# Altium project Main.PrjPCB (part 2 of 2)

## Sheet Main-6.SchDoc: #
size A3; ApprovedBy: #; DrawnBy: #; DocumentNumber: 6; Revision: #; SheetNumber: 6; DocumentRevision: #; Reviewed: #; QA: #; CM: #; ECR: #; PageSetup: Record=PageOptions¦CenterHorizontal=True¦CenterVertical=True¦PrintScale=0.97¦XCorrection=1.00¦YCorrection=1.00¦PrintKind=1¦BorderSize=5000000¦LeftOffset=0¦BottomOffset=0¦Orientation=2¦PaperLength=1000¦PaperWidth=1000¦Scale=100¦PaperSource=7¦PrintQuality=-4¦MediaType=1¦DitherType=10¦PaperKind=A3¦PrintScaleMode=1
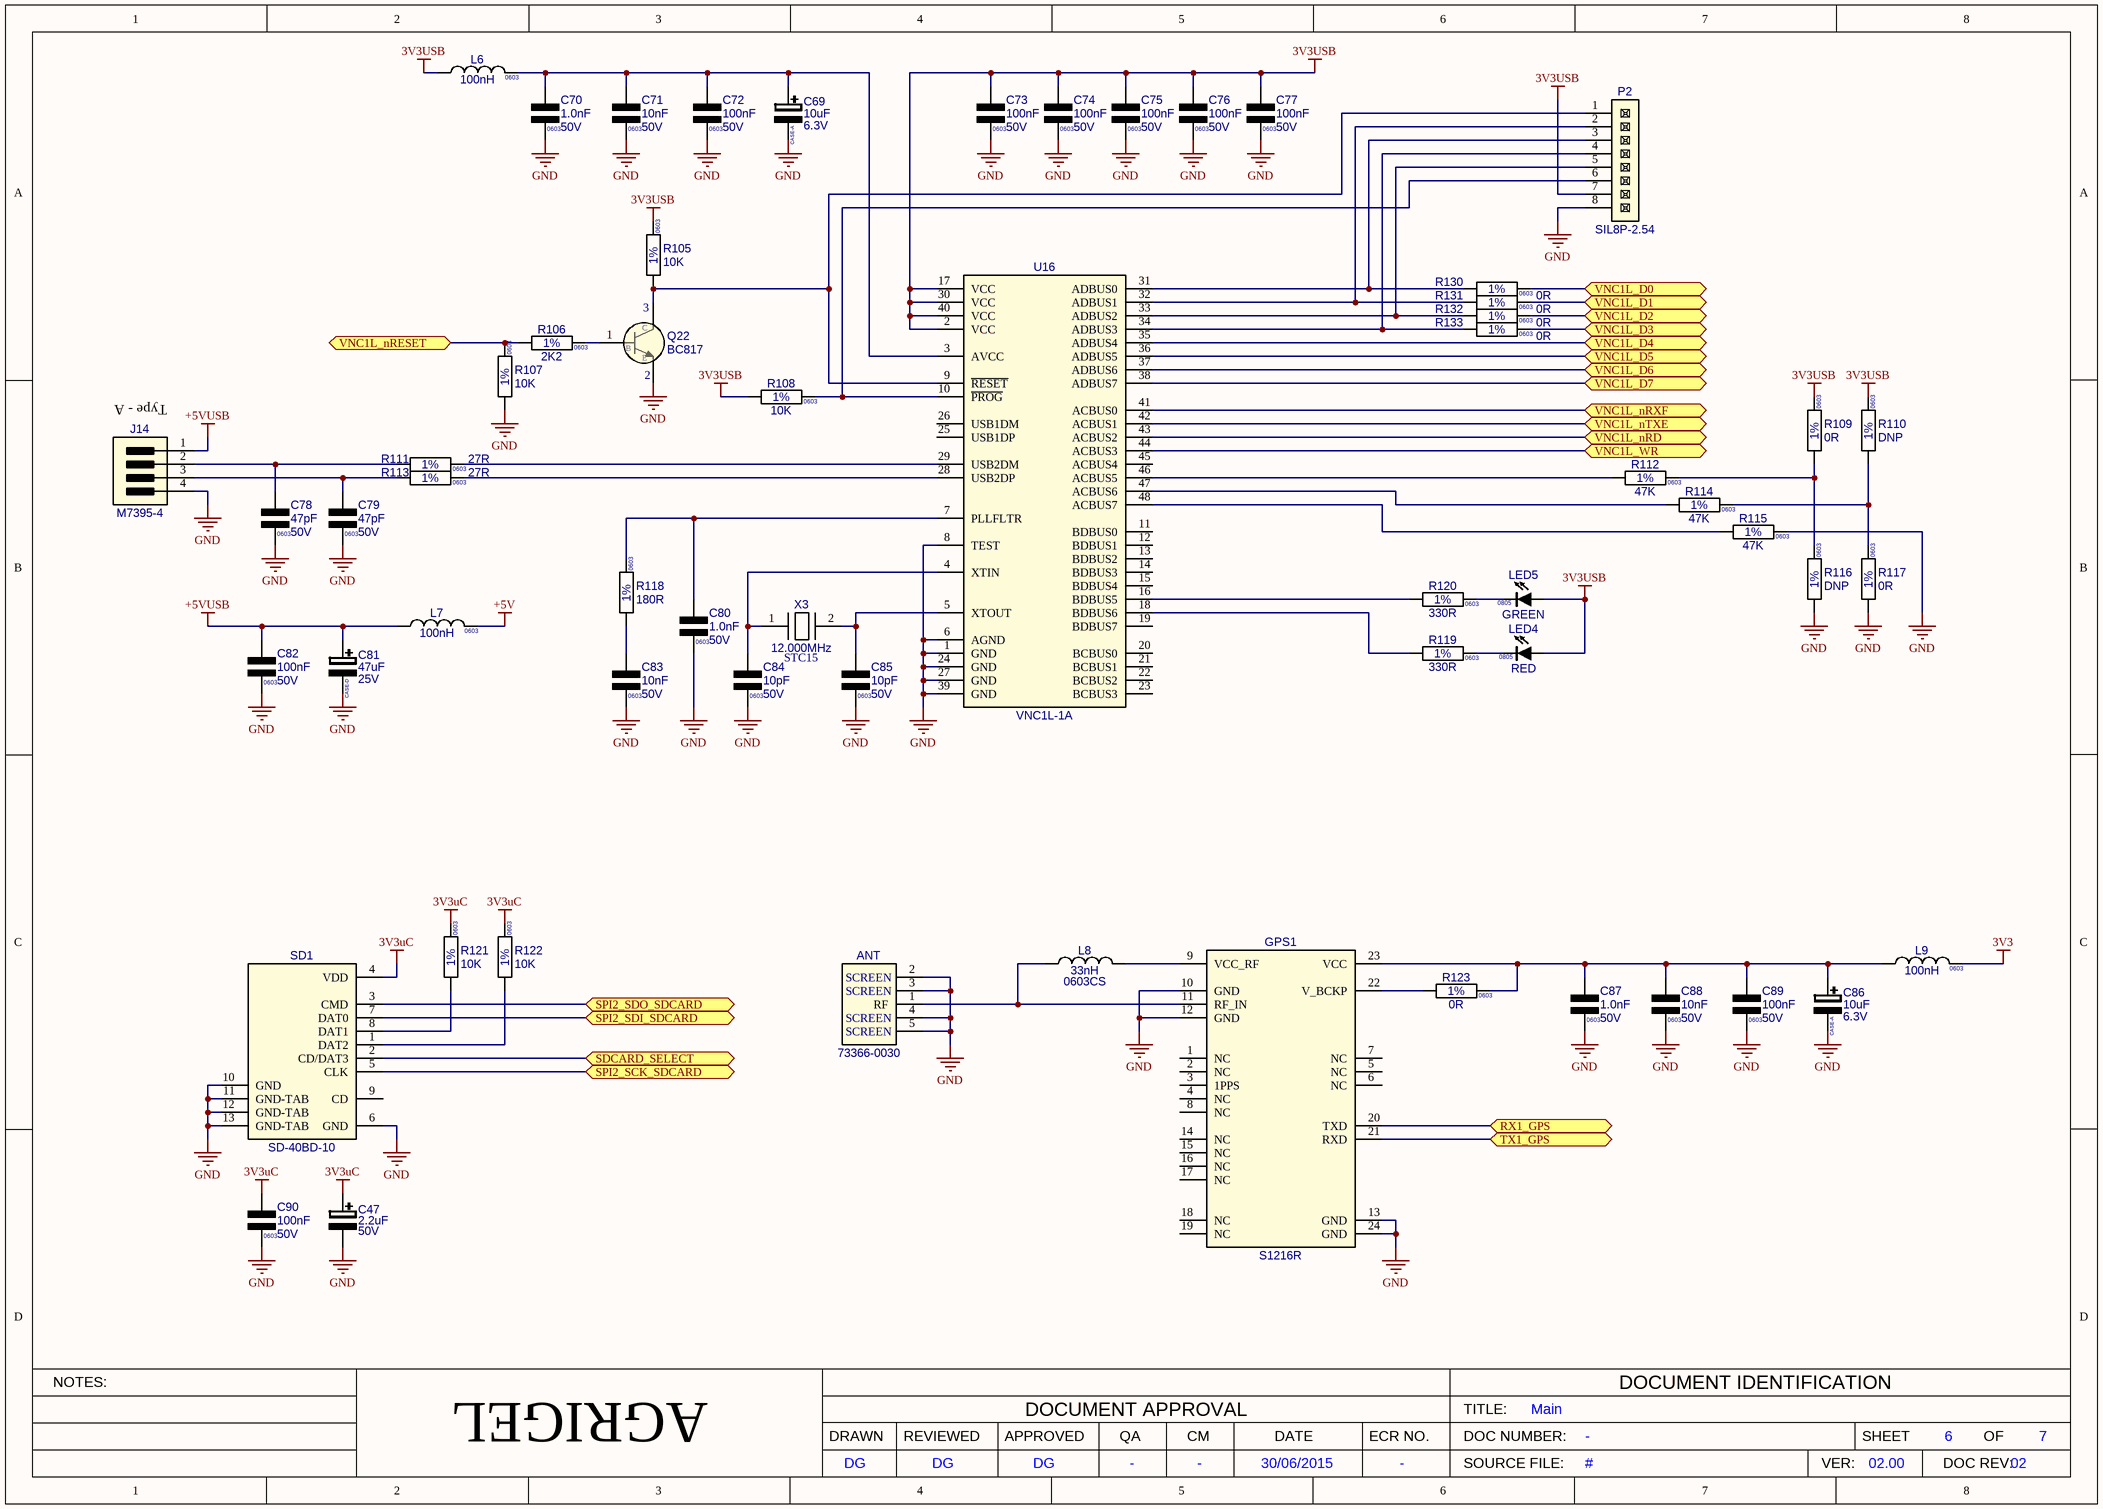
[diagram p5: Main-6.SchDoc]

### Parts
ANT  Part Number: 73366-0030  [MCX-RT-733660030]  (hidden comment: Coax-MCX-RT)
C47  value 2.2uF  Voltage: 50V  [CAP-EL-SMD-4X5.4]  (hidden comment: 2.2uF-50V-20%_4x5.4)
C69  value 10uF  Voltage: 6.3V  Text1: CASE-A  [T491-A]  (hidden comment: 10uF_6.3V_T491A_20%)
C70  value 1.0nF  Voltage: 50V  Text1: 0603  [CAPC0603X85N]  (hidden comment: 1.0nF_C0603_50V_10%_X7R)
C71  value 10nF  Voltage: 50V  Text1: 0603  [CAPC0603X85N]  (hidden comment: 10nF_C0603_50V_10%_X7R)
C72  value 100nF  Voltage: 50V  Text1: 0603  [CAPC0603X85N]  (hidden comment: 100nF_C0603_50V_5%_X7R)
C73  value 100nF  Voltage: 50V  Text1: 0603  [CAPC0603X85N]  (hidden comment: 100nF_C0603_50V_5%_X7R)
C74  value 100nF  Voltage: 50V  Text1: 0603  [CAPC0603X85N]  (hidden comment: 100nF_C0603_50V_5%_X7R)
C75  value 100nF  Voltage: 50V  Text1: 0603  [CAPC0603X85N]  (hidden comment: 100nF_C0603_50V_5%_X7R)
C76  value 100nF  Voltage: 50V  Text1: 0603  [CAPC0603X85N]  (hidden comment: 100nF_C0603_50V_5%_X7R)
C77  value 100nF  Voltage: 50V  Text1: 0603  [CAPC0603X85N]  (hidden comment: 100nF_C0603_50V_5%_X7R)
C78  value 47pF  Voltage: 50V  Text1: 0603  [CAPC0603X85N]  (hidden comment: 47pF_C0603_50V_10%_NP0)
C79  value 47pF  Voltage: 50V  Text1: 0603  [CAPC0603X85N]  (hidden comment: 47pF_C0603_50V_10%_NP0)
C80  value 1.0nF  Voltage: 50V  Text1: 0603  [CAPC0603X85N]  (hidden comment: 1.0nF_C0603_50V_10%_X7R)
C81  value 47uF  Voltage: 25V  Text1: CASE-D  [T491-D]  (hidden comment: 47uF_25V_T491D_20%)
C82  value 100nF  Voltage: 50V  Text1: 0603  [CAPC0603X85N]  (hidden comment: 100nF_C0603_50V_5%_X7R)
C83  value 10nF  Voltage: 50V  Text1: 0603  [CAPC0603X85N]  (hidden comment: 10nF_C0603_50V_10%_X7R)
C84  value 10pF  Voltage: 50V  Text1: 0603  [CAPC0603X85N]  (hidden comment: 10pF_C0603_50V_5%_NP0)
C85  value 10pF  Voltage: 50V  Text1: 0603  [CAPC0603X85N]  (hidden comment: 10pF_C0603_50V_5%_NP0)
C86  value 10uF  Voltage: 6.3V  Text1: CASE-A  [T491-A]  (hidden comment: 10uF_6.3V_T491A_20%)
C87  value 1.0nF  Voltage: 50V  Text1: 0603  [CAPC0603X85N]  (hidden comment: 1.0nF_C0603_50V_10%_X7R)
C88  value 10nF  Voltage: 50V  Text1: 0603  [CAPC0603X85N]  (hidden comment: 10nF_C0603_50V_10%_X7R)
C89  value 100nF  Voltage: 50V  Text1: 0603  [CAPC0603X85N]  (hidden comment: 100nF_C0603_50V_5%_X7R)
C90  value 100nF  Voltage: 50V  Text1: 0603  [CAPC0603X85N]  (hidden comment: 100nF_C0603_50V_5%_X7R)
GPS1  S1216R  [S1216R]
J14  M7395-4  [M7395-4]
L6  value 100nH  Text1: 0603  [L0603]  (hidden comment: 100nH-CI160808)
L7  value 100nH  Text1: 0603  [L0603]  (hidden comment: 100nH-CI160808)
L8  value 33nH  Text2: 0603CS  [L0603CS]  (hidden comment: 33nH-0603CS)
L9  value 100nH  Text1: 0603  [L0603]  (hidden comment: 100nH-CI160808)
LED4  value RED  Text2: 0805  [LED0805-Red]  (hidden comment: RED_0805_SMD)
LED5  value GREEN  Text2: 0805  [LED0805-Green]  (hidden comment: GREEN_0805_SMD)
P2  SIL8P-2.54  [SIL8P-2.54]
Q22  BC817  [SOT23]
R105  value 10K  Tol: 1%  Text1: 0603  [RESC0603X60N]  (hidden comment: 10K_R0603_1%)
R106  value 2K2  Tol: 1%  Text1: 0603  [RESC0603X60N]  (hidden comment: 2K2_R0603_1%)
R107  value 10K  Tol: 1%  Text1: 0603  [RESC0603X60N]  (hidden comment: 10K_R0603_1%)
R108  value 10K  Tol: 1%  Text1: 0603  [RESC0603X60N]  (hidden comment: 10K_R0603_1%)
R109  value 0R  Tol: 1%  Text1: 0603  [RESC0603X60N]  (hidden comment: 0R_R0603_1%)
R110  value DNP  Tol: 1%  Text1: 0603  [RESC0603X60N]  (hidden comment: DNP_R0603_1%)
R111  value 27R  Tol: 1%  Text1: 0603  [RESC0603X60N]  (hidden comment: 27R_R0603_1%)
R112  value 47K  Tol: 1%  Text1: 0603  [RESC0603X60N]  (hidden comment: 47K_R0603_1%)
R113  value 27R  Tol: 1%  Text1: 0603  [RESC0603X60N]  (hidden comment: 27R_R0603_1%)
R114  value 47K  Tol: 1%  Text1: 0603  [RESC0603X60N]  (hidden comment: 47K_R0603_1%)
R115  value 47K  Tol: 1%  Text1: 0603  [RESC0603X60N]  (hidden comment: 47K_R0603_1%)
R116  value DNP  Tol: 1%  Text1: 0603  [RESC0603X60N]  (hidden comment: DNP_R0603_1%)
R117  value 0R  Tol: 1%  Text1: 0603  [RESC0603X60N]  (hidden comment: 0R_R0603_1%)
R118  value 180R  Tol: 1%  Text1: 0603  [RESC0603X60N]  (hidden comment: 180R_R0603_1%)
R119  value 330R  Tol: 1%  Text1: 0603  [RESC0603X60N]  (hidden comment: 330R_R0603_1%)
R120  value 330R  Tol: 1%  Text1: 0603  [RESC0603X60N]  (hidden comment: 330R_R0603_1%)
R121  value 10K  Tol: 1%  Text1: 0603  [RESC0603X60N]  (hidden comment: 10K_R0603_1%)
R122  value 10K  Tol: 1%  Text1: 0603  [RESC0603X60N]  (hidden comment: 10K_R0603_1%)
R123  value 0R  Tol: 1%  Text1: 0603  [RESC0603X60N]  (hidden comment: 0R_R0603_1%)
R130  value 0R  Tol: 1%  Text1: 0603  [RESC0603X60N]  (hidden comment: 0R_R0603_1%)
R131  value 0R  Tol: 1%  Text1: 0603  [RESC0603X60N]  (hidden comment: 0R_R0603_1%)
R132  value 0R  Tol: 1%  Text1: 0603  [RESC0603X60N]  (hidden comment: 0R_R0603_1%)
R133  value 0R  Tol: 1%  Text1: 0603  [RESC0603X60N]  (hidden comment: 0R_R0603_1%)
SD1  SD-40BD-10  [SD-40BD-10]
U16  VNC1L-1A  [LQFP48-7x7]
X3  Text2: STC15  Text1: 12.000MHz  [XT-HEX15]  (hidden comment: XTAL_12.000MHz_STCX15)

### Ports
RX1_GPS, SDCARD_SELECT, SPI2_SCK_SDCARD, SPI2_SDI_SDCARD, SPI2_SDO_SDCARD, TX1_GPS, VNC1L_D0, VNC1L_D1, VNC1L_D2, VNC1L_D3, VNC1L_D4, VNC1L_D5, VNC1L_D6, VNC1L_D7, VNC1L_nRD, VNC1L_nRESET, VNC1L_nRXF, VNC1L_nTXE, VNC1L_WR

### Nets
3V3: L9.2
3V3uC: C47.1 C90.1 R121.1 R122.1 SD1.4(VDD)
3V3USB: C73.1 C74.1 C75.1 C76.1 C77.1 L6.1 LED4.2(A) LED5.2(A) P2.7 R105.1 R108.1 R109.1 R110.1 U16.2(VCC) U16.17(VCC) U16.30(VCC) U16.40(VCC)
+5V: L7.2
+5VUSB: C81.1 C82.1 J14.1 L7.1
GND: ANT.2(SCREEN) ANT.3(SCREEN) ANT.4(SCREEN) ANT.5(SCREEN) C47.2 C69.2 C70.2 C71.2 C72.2 C73.2 C74.2 C75.2 C76.2 C77.2 C78.2 C79.2 C80.2 C81.2 C82.2 C83.2 C84.2 C85.2 C86.2 C87.2 C88.2 C89.2 C90.2 GPS1.10(GND) GPS1.12(GND) GPS1.13(GND) GPS1.24(GND) J14.4 P2.8 Q22.2(E) R107.2 R115.2 R116.2 R117.2 SD1.6(GND) SD1.10(GND) SD1.11(GND-TAB) SD1.12(GND-TAB) SD1.13(GND-TAB) U16.1(GND) U16.6(AGND) U16.8(TEST) U16.24(GND) U16.27(GND) U16.39(GND)
NetANT_1: ANT.1(RF) GPS1.11(RF_IN) L8.1
NetC69_1: C69.1 C70.1 C71.1 C72.1 L6.2 U16.3(AVCC)
NetC78_1: C78.1 J14.2 R111.1
NetC79_1: C79.1 J14.3 R113.1
NetC80_1: C80.1 R118.1 U16.7(PLLFLTR)
NetC83_1: C83.1 R118.2
NetC84_1: C84.1 U16.4(XTIN) X3.1
NetC85_1: C85.1 U16.5(XTOUT) X3.2
NetC86_1: C86.1 C87.1 C88.1 C89.1 GPS1.23(VCC) L9.1 R123.2
NetGPS1_9: GPS1.9(VCC_RF) L8.2
NetGPS1_20: GPS1.20(TXD) ; port RX1_GPS
NetGPS1_21: GPS1.21(RXD) ; port TX1_GPS
NetGPS1_22: GPS1.22(V_BCKP) R123.1
NetLED4_1: LED4.1(K) R119.2
NetLED5_1: LED5.1(K) R120.2
NetP2_1: P2.1 Q22.3(C) R105.2 U16.9(~{RESET})
NetP2_2: P2.2 R131.1 U16.32(ADBUS1)
NetP2_3: P2.3 R130.1 U16.31(ADBUS0)
NetP2_4: P2.4 R133.1 U16.34(ADBUS3)
NetP2_5: P2.5 R132.1 U16.33(ADBUS2)
NetP2_6: P2.6 R108.2 U16.10(~{PROG})
NetQ22_1: Q22.1(B) R106.2
NetR106_1: R106.1 R107.1 ; port VNC1L_nRESET
NetR109_2: R109.2 R112.2 R116.1
NetR110_2: R110.2 R114.2 R117.1
NetR111_2: R111.2 U16.29(USB2DM)
NetR112_1: R112.1 U16.46(ACBUS5)
NetR113_2: R113.2 U16.28(USB2DP)
NetR114_1: R114.1 U16.47(ACBUS6)
NetR115_1: R115.1 U16.48(ACBUS7)
NetR119_1: R119.1 U16.18(BDBUS6)
NetR120_1: R120.1 U16.16(BDBUS5)
NetR121_2: R121.2 SD1.8(DAT1)
NetR122_2: R122.2 SD1.1(DAT2)
NetR130_2: R130.2 ; port VNC1L_D0
NetR131_2: R131.2 ; port VNC1L_D1
NetR132_2: R132.2 ; port VNC1L_D2
NetR133_2: R133.2 ; port VNC1L_D3
NetSD1_2: SD1.2(CD/DAT3) ; port SDCARD_SELECT
NetSD1_3: SD1.3(CMD) ; port SPI2_SDO_SDCARD
NetSD1_5: SD1.5(CLK) ; port SPI2_SCK_SDCARD
NetSD1_7: SD1.7(DAT0) ; port SPI2_SDI_SDCARD
NetU3_53: U16.43(ACBUS2) ; port VNC1L_nRD
NetU3_54: U16.44(ACBUS3) ; port VNC1L_WR
NetU3_55: U16.42(ACBUS1) ; port VNC1L_nTXE
NetU3_65: U16.35(ADBUS4) ; port VNC1L_D4
NetU3_66: U16.36(ADBUS5) ; port VNC1L_D5
NetU3_67: U16.37(ADBUS6) ; port VNC1L_D6
NetU3_68: U16.38(ADBUS7) ; port VNC1L_D7
NetU3_72: U16.41(ACBUS0) ; port VNC1L_nRXF

Not connected (* = marked no-connect by the designer): GPS1 1(NC) 2(NC) 3(1PPS) 4(NC) 5(NC) 6(NC) 7(NC) 8(NC) 14(NC) 15(NC) 16(NC) 17(NC) 18(NC) 19(NC); SD1 9(CD); U16 11(BDBUS0) 12(BDBUS1) 13(BDBUS2) 14(BDBUS3) 15(BDBUS4) 19(BDBUS7) 20(BCBUS0) 21(BCBUS1) 22(BCBUS2) 23(BCBUS3) 25(USB1DP) 26(USB1DM) 45(ACBUS4)

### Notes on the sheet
- (near J14) Type - A

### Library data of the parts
ANT = Coax-MCX-73366-0030: Connector Coax MCX Rt Angle 50Ohm; Manufacturer: Molex; Board Tech: THP
C47 = 2.2uF-50V-20%_4x5.4_V: Cap Electrolytic SMD (4x5.4); Manufacturer: Various; Part Number: Cap El SMD 2.2uF-50V-20%_4x5.4; Tol: 20%
C69 C86 = 10uF_6.3V_CASE-A_20%_V: Cap Tantalum Case-A; Manufacturer: Various; Board Tech: SMD; Tol: 20%
C70 C80 C87 = 1nF_0603N_50V_10%_X7R_V: Cap Ceramic X7R; Manufacturer: Various; Part Number: 1.0nF 0603 50V 10% X7R; Board Tech: SMD; Tol: 10%; Reutech PN: 5910-CA-0401
C71 C83 C88 = 10nF_0603N_50V_10%_X7R_V: Cap Ceramic X7R; Manufacturer: Various; Part Number: 10nF 0603 50V 10% X7R; Board Tech: SMD; Tol: 10%; Reutech PN: 5910-CA-0402
C72-C77 C82 C89 C90 = 100nF_0603N_50V_5%_X7R_V: Cap Ceramic X7R; Manufacturer: Various; Part Number: 100nF 0603 50V 5% X7R; Board Tech: SMD; Tol: 5%; Reutech PN: 5910-CA-0433
C78 C79 = 47pF_0603N_50V_10%_NP0_V: Cap Ceramic NP0; Manufacturer: Various; Part Number: 47pF 0603 50V 10% NP0; Board Tech: SMD; Tol: 10%
C81 = 47uF_25V_CASE-D_20%_V: Cap Tantalum Case-D; Manufacturer: Various; Board Tech: SMD; Tol: 20%
C84 C85 = 10pF_0603N_50V_5%_NP0_V: Cap Ceramic NP0; Manufacturer: Various; Part Number: 10pF 0603 50V 5% NP0; Board Tech: SMD; Tol: 5%
GPS1 = S1216R GPS Receiver: Module GPS Receiver; Manufacturer: SkyTraq; Board Tech: SMD
J14 = M7395-4: Header Pluggable 2.54mm Rt Angle Friction Lock; Manufacturer: Molex; Board Tech: THP
L6 L7 L9 = 100nH_CI160808_H: Inductor Chip SMD; Manufacturer: Bourns; Part Number: CI160808-R10J; Tol: 5%
L8 = 33nH_0603CS_5%_H: Inductor Chip SMD; Manufacturer: COILCRAFT; Part Number: 0603CS-33NXJL; Tol: 5%
LED4 = RED_0805_SMD_H: LED SMD 0805 Red; Manufacturer: Various; EDM-PN: LED7
LED5 = GREEN_0805_SMD_H: LED SMD 0805 Green; Manufacturer: Various; EDM-PN: LED17
P2 = SIL8P-2.54: Header SIL Male THP, 2.54mm Pitch; Manufacturer: Various
Q22 = BC817_SOT23: Transistor NPN General Purpose; Manufacturer: Various; Board Tech: SMD; EDM-PN: TRN12
R105 R107 R121 R122 = 10K_0603_V: Resistor Chip SMD; Manufacturer: Various; Part Number: 10K 0603 1%; Watt: 100mW; EDM-PN: RES120
R106 = 2K2_0603_H: Resistor Chip SMD; Manufacturer: Various; Part Number: 2K2 0603 1%; Watt: 100mW; EDM-PN: RES232
R108 = 10K_0603_H: Resistor Chip SMD; Manufacturer: Various; Part Number: 10K 0603 1%; Watt: 100mW; EDM-PN: RES120
R109 R117 = 0R_0603_V: Resistor Chip SMD; Manufacturer: Various; Part Number: 0R 0603 1%; Watt: 100mW; EDM-PN: RES117
R110 R116 = DNP_0603_V: Resistor Chip SMD; Manufacturer: Various; Watt: 100mW
R111 R113 = 27R_0603_H: Resistor Chip SMD; Manufacturer: Various; Part Number: 27R 0603 1%; Watt: 100mW; EDM-PN: RES619
R112 R114 R115 = 47K_0603_H: Resistor Chip SMD; Manufacturer: Various; Part Number: 47K 0603 1%; Watt: 100mW; EDM-PN: RES128
R118 = 180R_0603_V: Resistor Chip SMD; Manufacturer: Various; Part Number: 180R 0603 1%; Watt: 100mW
R119 R120 = 330R_0603_H: Resistor Chip SMD; Manufacturer: Various; Part Number: 330R 0603 1%; Watt: 100mW
R123 = 0R_0603_H: Resistor Chip SMD; Manufacturer: Various; Part Number: 0R 0603 1%; Watt: 100mW; EDM-PN: RES117
R130-R133 = 0r_0603_H: Resistor Chip SMD; Manufacturer: Various; Part Number: 0R 0603 1%; Watt: 100mW; EDM-PN: RES117
SD1 = SD-40BD-10: SD Micro Push-Push; Manufacturer: Speccon; Board Tech: SMD
U16 = VNC1L-1A-LQFP48: IC Dual USB Host Controller; Manufacturer: FTDI; Board Tech: SMT
X3 = XTAL_12.000MHz_STCX15: Crystal - HEX15; Manufacturer: STC; Part Number: STCX15-12.000MHz; Board Tech: SMD; Value: XTAL_STCX15-12.000MHz

## Sheet Main-7.SchDoc: #
size A3; ApprovedBy: #; DrawnBy: #; DocumentNumber: 7; Revision: #; SheetNumber: 7; DocumentRevision: #; Reviewed: #; QA: #; CM: #; ECR: #; PageSetup: Record=PageOptions|CenterHorizontal=True|CenterVertical=True|PrintScale=0.97|XCorrection=1.00|YCorrection=1.00|PrintKind=1|BorderSize=5000000|LeftOffset=0|BottomOffset=0|Orientation=2|PaperLength=1000|PaperWidth=1000|Scale=100|PaperSource=7|PrintQuality=-4|MediaType=1|DitherType=10|PaperKind=A3|PrintScaleMode=1
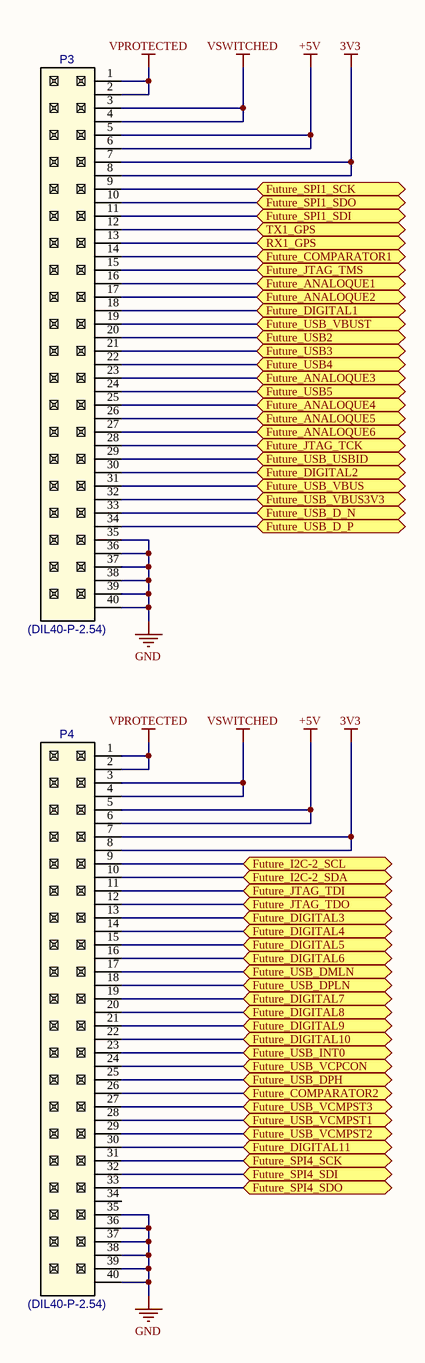
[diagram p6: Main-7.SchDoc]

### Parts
P3  value (DIL40-P-2.54)  [DIL40-P-2.54]  (hidden comment: DIL40P-2.54-DNF)
P4  value (DIL40-P-2.54)  [DIL40-P-2.54]  (hidden comment: DIL40P-2.54-DNF)

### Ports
Future_ANALOQUE1, Future_ANALOQUE2, Future_ANALOQUE3, Future_ANALOQUE4, Future_ANALOQUE5, Future_ANALOQUE6, Future_COMPARATOR1, Future_COMPARATOR2, Future_DIGITAL1, Future_DIGITAL2, Future_DIGITAL3, Future_DIGITAL4, Future_DIGITAL5, Future_DIGITAL6, Future_DIGITAL7, Future_DIGITAL8, Future_DIGITAL9, Future_DIGITAL10, Future_DIGITAL11, Future_I2C-2_SCL, Future_I2C-2_SDA, Future_JTAG_TCK, Future_JTAG_TDI, Future_JTAG_TDO, Future_JTAG_TMS, Future_SPI1_SCK, Future_SPI1_SDI, Future_SPI1_SDO, Future_SPI4_SCK, Future_SPI4_SDI, Future_SPI4_SDO, Future_USB2, Future_USB3, Future_USB4, Future_USB5, Future_USB_D_N, Future_USB_D_P, Future_USB_DMLN, Future_USB_DPH, Future_USB_DPLN, Future_USB_INT0, Future_USB_USBID, Future_USB_VBUS, Future_USB_VBUS3V3, Future_USB_VBUST, Future_USB_VCMPST1, Future_USB_VCMPST2, Future_USB_VCMPST3, Future_USB_VCPCON, RX1_GPS, TX1_GPS

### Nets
3V3: P3.7 P3.8 P4.7 P4.8
+5V: P3.5 P3.6 P4.5 P4.6
GND: P3.35 P3.36 P3.37 P3.38 P3.39 P3.40 P4.35 P4.36 P4.37 P4.38 P4.39 P4.40
VPROTECTED: P3.1 P3.2 P4.1 P4.2
VSWITCHED: P3.3 P3.4 P4.3 P4.4
NetGPS1_20: P3.13 ; port RX1_GPS
NetGPS1_21: P3.12 ; port TX1_GPS
NetP3_9: P3.9 ; port Future_SPI1_SCK
NetP3_10: P3.10 ; port Future_SPI1_SDO
NetP3_11: P3.11 ; port Future_SPI1_SDI
NetP3_14: P3.14 ; port Future_COMPARATOR1
NetP3_15: P3.15 ; port Future_JTAG_TMS
NetP3_16: P3.16 ; port Future_ANALOQUE1
NetP3_17: P3.17 ; port Future_ANALOQUE2
NetP3_18: P3.18 ; port Future_DIGITAL1
NetP3_19: P3.19 ; port Future_USB_VBUST
NetP3_20: P3.20 ; port Future_USB2
NetP3_21: P3.21 ; port Future_USB3
NetP3_22: P3.22 ; port Future_USB4
NetP3_23: P3.23 ; port Future_ANALOQUE3
NetP3_24: P3.24 ; port Future_USB5
NetP3_25: P3.25 ; port Future_ANALOQUE4
NetP3_26: P3.26 ; port Future_ANALOQUE5
NetP3_27: P3.27 ; port Future_ANALOQUE6
NetP3_28: P3.28 ; port Future_JTAG_TCK
NetP3_29: P3.29 ; port Future_USB_USBID
NetP3_30: P3.30 ; port Future_DIGITAL2
NetP3_31: P3.31 ; port Future_USB_VBUS
NetP3_32: P3.32 ; port Future_USB_VBUS3V3
NetP3_33: P3.33 ; port Future_USB_D_N
NetP3_34: P3.34 ; port Future_USB_D_P
NetP4_9: P4.9 ; port Future_I2C-2_SCL
NetP4_10: P4.10 ; port Future_I2C-2_SDA
NetP4_11: P4.11 ; port Future_JTAG_TDI
NetP4_12: P4.12 ; port Future_JTAG_TDO
NetP4_13: P4.13 ; port Future_DIGITAL3
NetP4_14: P4.14 ; port Future_DIGITAL4
NetP4_15: P4.15 ; port Future_DIGITAL5
NetP4_16: P4.16 ; port Future_DIGITAL6
NetP4_17: P4.17 ; port Future_USB_DMLN
NetP4_18: P4.18 ; port Future_USB_DPLN
NetP4_19: P4.19 ; port Future_DIGITAL7
NetP4_20: P4.20 ; port Future_DIGITAL8
NetP4_21: P4.21 ; port Future_DIGITAL9
NetP4_22: P4.22 ; port Future_DIGITAL10
NetP4_23: P4.23 ; port Future_USB_INT0
NetP4_24: P4.24 ; port Future_USB_VCPCON
NetP4_25: P4.25 ; port Future_USB_DPH
NetP4_26: P4.26 ; port Future_COMPARATOR2
NetP4_27: P4.27 ; port Future_USB_VCMPST3
NetP4_28: P4.28 ; port Future_USB_VCMPST1
NetP4_29: P4.29 ; port Future_USB_VCMPST2
NetP4_30: P4.30 ; port Future_DIGITAL11
NetP4_31: P4.31 ; port Future_SPI4_SCK
NetP4_32: P4.32 ; port Future_SPI4_SDI
NetP4_33: P4.33 ; port Future_SPI4_SDO

Not connected (* = marked no-connect by the designer): P4 34

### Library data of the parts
P3 P4 = DIL40P-2.54-DNF: Header Male Straight, 2.54mm Pitch - Do not Fit; Manufacturer: Various; Part Number: DNF - DIL40-P-2.54; Board Tech: THP

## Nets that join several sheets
3V3: Main-1 (7 pins), Main-6 (L9.2), Main-7 (P3.7 P3.8 P4.7 P4.8)
3V3uC: Main-1 (5 pins), Main-2 (21 pins), Main-4 (20 pins), Main-6 (5 pins)
3V3USB: Main-1 (5 pins), Main-6 (17 pins)
+5V: Main-1 (C4.1 L1.2 R2.1 R3.1), Main-2 (R15.1), Main-3 (12 pins), Main-5 (19 pins), Main-6 (L7.2), Main-7 (P3.5 P3.6 P4.5 P4.6)
GND: Main-1 (37 pins), Main-2 (30 pins), Main-3 (47 pins), Main-4 (28 pins), Main-5 (32 pins), Main-6 (49 pins), Main-7 (12 pins)
VPROTECTED: Main-1 (8 pins), Main-5 (K2.4 K2.13 Q19.2 R96.1), Main-7 (P3.1 P3.2 P4.1 P4.2)
VSLAVES: Main-1 (K1.8 K1.9), Main-3 (J5.1 J7.1)
VSWITCHED: Main-1 (D5.2 D8.2), Main-2 (R16.1), Main-3 (5 pins), Main-5 (6 pins), Main-7 (P3.3 P3.4 P4.3 P4.4)
NetD16_2: Main-2 (U3.6), Main-5 (D16.2)
NetD18_2: Main-2 (U3.7), Main-5 (D18.2)
NetD21_2: Main-2 (U3.8), Main-5 (D21.2)
NetD23_2: Main-2 (U3.9), Main-5 (D23.2)
NetGPS1_20: Main-2 (U3.10), Main-6 (GPS1.20), Main-7 (P3.13)
NetGPS1_21: Main-2 (U3.5), Main-6 (GPS1.21), Main-7 (P3.12)
NetLCD1_4: Main-2 (U3.119), Main-5 (LCD1.4 R75.2)
NetLCD1_5: Main-2 (U3.114), Main-5 (LCD1.5 R76.2)
NetLCD1_6: Main-2 (U3.113), Main-5 (LCD1.6 R77.2)
NetLCD1_7: Main-2 (U3.115), Main-5 (LCD1.7 R78.2)
NetLCD1_8: Main-2 (U3.116), Main-5 (LCD1.8 R79.2)
NetLCD1_9: Main-2 (U3.117), Main-5 (LCD1.9 R80.2)
NetLCD1_10: Main-2 (U3.118), Main-5 (LCD1.10 R81.2)
NetLCD1_11: Main-2 (U3.132), Main-5 (LCD1.11 R82.2)
NetLCD1_12: Main-2 (U3.133), Main-5 (LCD1.12 R83.2)
NetLCD1_13: Main-2 (U3.134), Main-5 (LCD1.13 R84.2)
NetLCD1_14: Main-2 (U3.135), Main-5 (LCD1.14 R85.2)
NetLCD1_15: Main-2 (U3.120), Main-5 (LCD1.15 R86.2)
NetLCD1_16: Main-2 (U3.138), Main-5 (LCD1.16 R88.2)
NetLCD-SPR1_1: Main-2 (U3.139), Main-5 (LCD-SPR1.1)
NetLCD-SPR2_1: Main-2 (U3.140), Main-5 (LCD-SPR2.1)
NetP3_9: Main-2 (U3.1), Main-7 (P3.9)
NetP3_10: Main-2 (U3.3), Main-7 (P3.10)
NetP3_11: Main-2 (U3.4), Main-7 (P3.11)
NetP3_14: Main-2 (U3.20), Main-7 (P3.14)
NetP3_15: Main-2 (U3.25), Main-7 (P3.15)
NetP3_16: Main-2 (U3.26), Main-7 (P3.16)
NetP3_17: Main-2 (U3.27), Main-7 (P3.17)
NetP3_18: Main-2 (U3.28), Main-7 (P3.18)
NetP3_19: Main-2 (U3.30), Main-7 (P3.19)
NetP3_20: Main-2 (U3.31), Main-7 (P3.20)
NetP3_21: Main-2 (U3.32), Main-7 (P3.21)
NetP3_22: Main-2 (U3.33), Main-7 (P3.22)
NetP3_23: Main-2 (U3.37), Main-7 (P3.23)
NetP3_24: Main-2 (U3.38), Main-7 (P3.24)
NetP3_25: Main-2 (U3.39), Main-7 (P3.25)
NetP3_26: Main-2 (U3.40), Main-7 (P3.26)
NetP3_27: Main-2 (U3.47), Main-7 (P3.27)
NetP3_28: Main-2 (U3.56), Main-7 (P3.28)
NetP3_29: Main-2 (U3.74), Main-7 (P3.29)
NetP3_30: Main-2 (U3.76), Main-7 (P3.30)
NetP3_31: Main-2 (U3.77), Main-7 (P3.31)
NetP3_32: Main-2 (R92.2 U3.78), Main-7 (P3.32)
NetP3_33: Main-2 (U3.79), Main-7 (P3.33)
NetP3_34: Main-2 (U3.80), Main-7 (P3.34)
NetP4_9: Main-2 (U3.85), Main-7 (P4.9)
NetP4_10: Main-2 (U3.86), Main-7 (P4.10)
NetP4_11: Main-2 (U3.87), Main-7 (P4.11)
NetP4_12: Main-2 (U3.88), Main-7 (P4.12)
NetP4_13: Main-2 (U3.93), Main-7 (P4.13)
NetP4_14: Main-2 (U3.94), Main-7 (P4.14)
NetP4_15: Main-2 (U3.95), Main-7 (P4.15)
NetP4_16: Main-2 (U3.96), Main-7 (P4.16)
NetP4_17: Main-2 (U3.97), Main-7 (P4.17)
NetP4_18: Main-2 (U3.98), Main-7 (P4.18)
NetP4_19: Main-2 (U3.99), Main-7 (P4.19)
NetP4_20: Main-2 (U3.100), Main-7 (P4.20)
NetP4_21: Main-2 (U3.101), Main-7 (P4.21)
NetP4_22: Main-2 (U3.104), Main-7 (P4.22)
NetP4_23: Main-2 (U3.105), Main-7 (P4.23)
NetP4_24: Main-2 (U3.109), Main-7 (P4.24)
NetP4_25: Main-2 (U3.110), Main-7 (P4.25)
NetP4_26: Main-2 (U3.121), Main-7 (P4.26)
NetP4_27: Main-2 (U3.122), Main-7 (P4.27)
NetP4_28: Main-2 (U3.126), Main-7 (P4.28)
NetP4_29: Main-2 (U3.127), Main-7 (P4.29)
NetP4_30: Main-2 (U3.131), Main-7 (P4.30)
NetP4_31: Main-2 (U3.142), Main-7 (P4.31)
NetP4_32: Main-2 (U3.143), Main-7 (P4.32)
NetP4_33: Main-2 (U3.144), Main-7 (P4.33)
NetQ4_3: Main-2 (U3.81), Main-3 (Q4.3 R26.2)
NetQ6_3: Main-2 (U3.82), Main-3 (Q6.3 R42.2)
NetQ9_3: Main-2 (U3.83), Main-3 (Q9.3 R52.2)
NetQ12_3: Main-2 (U3.84), Main-3 (Q12.3 R64.2)
NetQ17_3: Main-2 (U3.14), Main-5 (Q17.3)
NetQ18_3: Main-2 (U3.15), Main-5 (Q18.3)
NetQ20_3: Main-2 (U3.21), Main-5 (Q20.3)
NetR6_1: Main-1 (R6.1 R7.1), Main-2 (U3.103)
NetR23_2: Main-2 (U3.11), Main-3 (R23.2)
NetR31_2: Main-2 (U3.12), Main-3 (R31.2)
NetR39_2: Main-2 (U3.13), Main-3 (R39.2)
NetR47_2: Main-2 (U3.58), Main-3 (R47.2 U4.4)
NetR53_1: Main-2 (U3.59), Main-3 (R53.1 R56.1)
NetR60_2: Main-2 (U3.129), Main-3 (R60.2 U5.4)
NetR67_1: Main-2 (U3.130), Main-3 (R67.1 R71.1)
NetR73_1: Main-2 (U3.48), Main-4 (9 pins)
NetR74_2: Main-2 (U3.50), Main-4 (R74.2 U7.4)
NetR93_1: Main-2 (U3.111), Main-5 (R93.1 R94.1)
NetR103_1: Main-2 (U3.102), Main-5 (R103.1 R104.1)
NetR106_1: Main-2 (U3.75), Main-6 (R106.1 R107.1)
NetR130_2: Main-2 (U3.43), Main-6 (R130.2)
NetR131_2: Main-2 (U3.44), Main-6 (R131.2)
NetR132_2: Main-2 (U3.45), Main-6 (R132.2)
NetR133_2: Main-2 (U3.46), Main-6 (R133.2)
NetSD1_2: Main-2 (U3.22), Main-6 (SD1.2)
NetSD1_3: Main-2 (U3.18), Main-6 (SD1.3)
NetSD1_5: Main-2 (U3.16), Main-6 (SD1.5)
NetSD1_7: Main-2 (U3.17), Main-6 (SD1.7)
NetU3_49: Main-2 (U3.49), Main-4 (8 pins)
NetU3_53: Main-2 (U3.53), Main-6 (U16.43)
NetU3_54: Main-2 (U3.54), Main-6 (U16.44)
NetU3_55: Main-2 (U3.55), Main-6 (U16.42)
NetU3_57: Main-2 (U3.57), Main-3 (U4.1)
NetU3_60: Main-2 (U3.60), Main-4 (U7.1)
NetU3_61: Main-2 (U3.61), Main-4 (U7.2)
NetU3_62: Main-2 (U3.62), Main-4 (U7.3)
NetU3_65: Main-2 (U3.65), Main-6 (U16.35)
NetU3_66: Main-2 (U3.66), Main-6 (U16.36)
NetU3_67: Main-2 (U3.67), Main-6 (U16.37)
NetU3_68: Main-2 (U3.68), Main-6 (U16.38)
NetU3_69: Main-2 (U3.69), Main-4 (8 pins)
NetU3_70: Main-2 (U3.70), Main-4 (8 pins)
NetU3_71: Main-2 (U3.71), Main-4 (8 pins)
NetU3_72: Main-2 (U3.72), Main-6 (U16.41)
NetU3_128: Main-2 (U3.128), Main-3 (U5.1)
NetU3_136: Main-2 (U3.136), Main-5 (U15.2)
NetU3_137: Main-2 (U3.137), Main-5 (U15.30)

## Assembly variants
Variant of Main: not fitted C33 C34 C43 C45 Q6 Q7 Q10 Q13X Q15X R10 R13 R15 R32 R33 R35 R44 R45 R46 R50 R51 R52 R55 R63 R64 R65 R66 R110 R116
